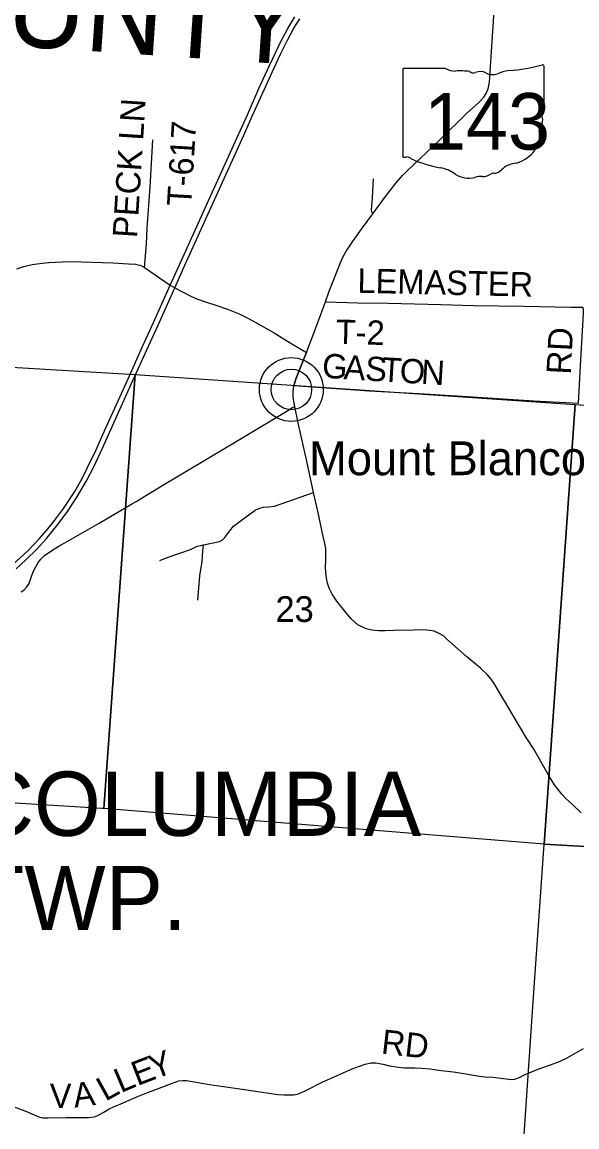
# Model space of a CAD drawing. Extents: x 0 to 34, y 0 to 22.
# Drawn here: x 6.101 to 7.394, y 18.062 to 20.64 of the extents above; entities that cross this region are included whole.
import ezdxf

# ---------------------------------------------------------------- set-up
doc = ezdxf.new("R2010")
doc.units = 0
for name, color, linetype in [('GM_X_Corporation', 7, 'Continuous'), ('GM_X_County_Road', 7, 'Continuous'), ('GM_X_County_Text', 7, 'Continuous'), ('GM_X_Section_Text', 7, 'Continuous'), ('GM_X_State_Location', 7, 'Continuous'), ('GM_X_State_Route', 7, 'Continuous'), ('GM_X_State_Shield', 7, 'Continuous'), ('GM_X_Township_Road', 7, 'Continuous'), ('GM_X_Township_Road_Text', 7, 'Continuous'), ('GM_X_Township_Text', 7, 'Continuous'), ('GM_X_Unincorporated', 7, 'Continuous'), ('GM_X_Unincorporated_Location', 7, 'Continuous'), ('GM_X_Unincorporated_Text', 7, 'Continuous')]:
    doc.layers.add(name, color=color, linetype=linetype)

msp = doc.modelspace()

# ---------------------------------------------------------------- linework, layer by layer
at = {"layer": 'GM_X_Corporation'}
for points in [[(6.3643, 19.8173), (6.291, 18.8048), (6.2863, 18.8051), (5.2756, 18.8667), (5.342, 19.878)], [(6.3643, 19.8173), (7.3904, 19.7475), (7.3179, 18.7214), (6.291, 18.8048)], [(7.3904, 19.7475), (8.4063, 19.6773), (8.3303, 18.6644), (7.3179, 18.7214)], [(7.3179, 18.7214), (8.3303, 18.6644), (8.2967, 18.2357), (8.2648, 17.8281), (8.2474, 17.6405), (7.6907, 17.673), (7.2488, 17.7032), (7.2611, 17.894), (7.2923, 18.3534)]]:
    msp.add_lwpolyline(points, close=True, dxfattribs=at)
at = {"layer": 'GM_X_County_Road'}
for points in [[(6.1988, 19.4239), (6.28, 19.4706), (6.3577, 19.5168), (6.3662, 19.5214), (6.4284, 19.5592), (6.4905, 19.5959), (6.6033, 19.6637), (6.7203, 19.7333), (6.731, 19.7408), (6.7363, 19.7428)], [(6.0981, 19.3103), (6.1045, 19.3142), (6.1111, 19.3214), (6.1162, 19.3284), (6.1264, 19.3567), (6.1323, 19.3689), (6.1381, 19.3792), (6.1445, 19.3869), (6.1532, 19.3952), (6.1702, 19.4072), (6.185, 19.416), (6.1988, 19.4239)]]:
    msp.add_lwpolyline(points, dxfattribs=at)
at = {"layer": 'GM_X_State_Route'}
for points in [[(6.8765, 20.1348), (6.8917, 20.1563), (6.9187, 20.1927), (6.9454, 20.2299), (6.972, 20.264), (6.9879, 20.2817), (6.9976, 20.2919), (7.0749, 20.3652), (7.1375, 20.4273), (7.1647, 20.4515), (7.1775, 20.4643), (7.1829, 20.4732), (7.1873, 20.4837), (7.1902, 20.4999), (7.1949, 20.5711), (7.2038, 20.701), (7.211, 20.7857)], [(6.067, 19.3632), (6.1157, 19.408), (6.1404, 19.434), (6.1572, 19.4536), (6.1766, 19.4773), (6.1953, 19.5027), (6.2233, 19.5449), (6.2397, 19.5735), (6.2519, 19.5972), (6.2724, 19.6402), (6.2887, 19.6773), (6.3361, 19.782), (6.3482, 19.8077), (6.3817, 19.8831), (6.4069, 19.939), (6.4458, 20.0256), (6.4674, 20.0733), (6.5366, 20.2263), (6.5942, 20.3534), (6.6013, 20.3691), (6.6258, 20.4236), (6.653, 20.4845), (6.6775, 20.5388), (6.7046, 20.5958), (6.7204, 20.6247), (6.7367, 20.6518)], [(6.087, 19.3643), (6.1094, 19.3847), (6.135, 19.4101), (6.1576, 19.4351), (6.1843, 19.4676), (6.2064, 19.498), (6.2278, 19.5294), (6.2511, 19.5694), (6.2685, 19.6039), (6.2877, 19.6453), (6.355, 19.7949), (6.4037, 19.9024), (6.4141, 19.9238), (6.4568, 20.0197), (6.4804, 20.0729), (6.5496, 20.2252), (6.618, 20.376), (6.6373, 20.4204), (6.6842, 20.5243), (6.7031, 20.5648), (6.7193, 20.5975), (6.7343, 20.6255), (6.7479, 20.6473)], [(6.7636, 19.869), (6.7903, 19.939), (6.8078, 19.987), (6.8167, 20.012), (6.8442, 20.0805), (6.8485, 20.0913), (6.8555, 20.1035), (6.8712, 20.1274), (6.8765, 20.1348)], [(6.7345, 19.7916), (6.7399, 19.8093), (6.7613, 19.8636), (6.7636, 19.869)], [(7.4042, 18.795), (7.3853, 18.8123), (7.3687, 18.8283), (7.3595, 18.838), (7.3422, 18.8597), (7.3296, 18.8801), (7.2937, 18.9433), (7.2763, 18.9708), (7.2462, 19.0206), (7.2013, 19.0967), (7.1941, 19.1065), (7.1856, 19.1164), (7.1692, 19.132), (7.1374, 19.1589), (7.1042, 19.1882), (7.0911, 19.2001), (7.083, 19.2076), (7.0734, 19.2133), (7.0614, 19.2184), (7.051, 19.2205), (7.0371, 19.2215), (7.0136, 19.2213), (6.9673, 19.2203), (6.9475, 19.2197), (6.9314, 19.2196), (6.9161, 19.2207), (6.9031, 19.2239), (6.8837, 19.2333), (6.868, 19.2474), (6.8529, 19.2655), (6.8346, 19.289), (6.8237, 19.3053), (6.817, 19.3188), (6.8131, 19.331), (6.8103, 19.343), (6.8087, 19.3547), (6.8084, 19.3681), (6.8087, 19.3842), (6.8089, 19.401), (6.8085, 19.4112), (6.8066, 19.4234), (6.8027, 19.4393), (6.7899, 19.4987), (6.7803, 19.5424), (6.7642, 19.6155), (6.7454, 19.7012), (6.7363, 19.7428), (6.7345, 19.7548), (6.733, 19.767), (6.733, 19.7769), (6.7332, 19.7843), (6.7345, 19.7916)]]:
    msp.add_lwpolyline(points, dxfattribs=at)
at = {"layer": 'GM_X_State_Shield'}
for p, q in [((6.988, 20.5284), (6.988, 20.3283)), ((7.0878, 20.5318), (6.9913, 20.5318)), ((7.3176, 20.4321), (7.3176, 20.5368)), ((7.3176, 20.4321), (7.3176, 20.4321))]:
    msp.add_line(p, q, dxfattribs=at)
for centre, major_axis, start_param, end_param in [((6.9918, 20.5288), (0.00382, 0), 1.712693, 3.28349), ((7.1108, 20.5551), (0.037, 0), 4.042523, 4.731795), ((7.1231, 20.4195), (0.133, 0), 1.404758, 1.657858), ((7.1532, 20.5299), (0.0107, 0), 3.836095, 5.185415), ((7.1689, 20.5067), (0.0222, 0), 0.950623, 2.079405), ((7.1976, 20.5385), (0.0267, 0), 4.081561, 5.145723), ((7.2448, 20.4707), (0.0703, 0), 1.699011, 2.107814), ((7.2002, 20.8047), (0.3495, 0), 4.814394, 5.042369), ((7.314, 20.5372), (0.00367, 0), 6.141152, 7.989035), ((7.3168, 20.4244), (0.00568, 0), 1.883978, 3.671073), ((7.2806, 20.4112), (0.0341, 0), 5.934695, 6.695948), ((7.3137, 20.4317), (0.00393, 0), 5.05454, 6.418171), ((7.3308, 20.3883), (0.0248, 0), 2.387724, 3.262537), ((7.2198, 20.375), (0.0874, 0), 5.101752, 6.440018), ((6.9918, 20.3278), (0.00385, 0), 3.00124, 4.508301), ((6.9924, 20.3483), (0.0294, 0), 4.665946, 4.897461), ((6.9984, 20.3167), (0.0106, 0), 0.519207, 1.627899), ((7.1323, 20.4965), (0.2524, 0), 4.195997, 4.488961), ((7.057, 20.2384), (0.079, 0), 0.823519, 1.323587), ((7.196, 20.3089), (0.0282, 0), 4.937069, 5.64225), ((7.2567, 20.2721), (0.0479, 0), 1.647645, 2.488434), ((7.1424, 20.3157), (0.0501, 0), 4.026481, 4.996735), ((7.1714, 20.2466), (0.0412, 0), 1.495662, 1.94098), ((7.175, 20.3008), (0.0267, 0), 4.691044, 5.507374), ((7.1992, 20.2814), (0.00752, 0), 1.147584, 2.315152)]:
    msp.add_ellipse(centre, major_axis=major_axis, ratio=0.8, start_param=start_param, end_param=end_param, dxfattribs=at)
at = {"layer": 'GM_X_Township_Road'}
msp.add_line((6.3861, 20.0674), (6.4458, 20.0256), dxfattribs=at)
for points in [[(6.3861, 20.0674), (6.3904, 20.1213), (6.3925, 20.1594), (6.3991, 20.255), (6.4057, 20.365)], [(6.9187, 20.1927), (6.9164, 20.1973), (6.915, 20.2014), (6.9173, 20.2305), (6.9196, 20.2737)], [(6.0885, 20.0641), (6.1048, 20.0698), (6.1242, 20.074), (6.1475, 20.0775), (6.1628, 20.0788), (6.1937, 20.0805), (6.2152, 20.0814), (6.3125, 20.0778), (6.3485, 20.076), (6.3648, 20.075), (6.3707, 20.0737), (6.3753, 20.0726), (6.3789, 20.0709), (6.3861, 20.0674)], [(6.4458, 20.0256), (6.4568, 20.0197), (6.4912, 20.0016), (6.5058, 19.9952), (6.5285, 19.9872), (6.5548, 19.9783), (6.5798, 19.97), (6.607, 19.9587), (6.6289, 19.9481), (6.6508, 19.9357), (6.688, 19.9145), (6.7256, 19.8913), (6.7636, 19.869)], [(6.8078, 19.987), (6.8835, 19.9849), (6.955, 19.9837), (7.0769, 19.9809), (7.1529, 19.9784), (7.2703, 19.9768), (7.3804, 19.9749), (7.408, 19.9745)], [(6.7345, 19.7916), (6.8105, 19.7864), (6.91, 19.7796), (7.0256, 19.7732), (7.1508, 19.7653), (7.198, 19.7624), (7.2941, 19.7563), (7.3981, 19.7503), (7.4029, 19.8375), (7.41, 19.9599), (7.41, 19.9692), (7.408, 19.9745)], [(6.7636, 19.869), (6.7613, 19.8636), (6.7399, 19.8093), (6.7345, 19.7916)], [(6.5226, 19.4201), (6.5236, 19.4203), (6.5611, 19.4279), (6.5673, 19.4307), (6.5735, 19.4374), (6.5849, 19.4526), (6.5939, 19.464), (6.6091, 19.4754), (6.6442, 19.501), (6.6523, 19.5048), (6.6627, 19.5076), (6.676, 19.5091), (6.6893, 19.51), (6.7803, 19.5424)], [(6.4215, 19.3837), (6.4353, 19.3889), (6.4566, 19.397), (6.478, 19.4036), (6.4951, 19.4103), (6.5089, 19.4169), (6.517, 19.4188), (6.5226, 19.4201)], [(6.5103, 19.2906), (6.5151, 19.3481), (6.5203, 19.3813), (6.5222, 19.4051), (6.5236, 19.4203)], [(6.0732, 18.1122), (6.1007, 18.1016), (6.1146, 18.0963), (6.1303, 18.0891), (6.1397, 18.0852), (6.1487, 18.0834), (6.1609, 18.083), (6.2025, 18.0836), (6.219, 18.0836), (6.2553, 18.0842), (6.2694, 18.0854), (6.2773, 18.0883), (6.29, 18.0958), (6.3037, 18.1042), (6.3141, 18.1085), (6.3289, 18.1146), (6.3451, 18.1221), (6.372, 18.134), (6.3952, 18.1428), (6.4099, 18.1487), (6.4266, 18.1546), (6.4493, 18.1634), (6.4664, 18.1693), (6.4752, 18.1705), (6.4842, 18.1701), (6.4931, 18.1685), (6.5015, 18.1672), (6.5194, 18.1638), (6.5376, 18.1605), (6.619, 18.1489), (6.6551, 18.1434), (6.6973, 18.1377), (6.7108, 18.1368), (6.7234, 18.1364), (6.7346, 18.1368), (6.7418, 18.1383), (6.7503, 18.1417), (6.764, 18.1479), (6.8001, 18.1662), (6.8284, 18.1786), (6.87, 18.1974), (6.8874, 18.2039), (6.9002, 18.2086), (6.9141, 18.2111), (6.9245, 18.2117), (6.9429, 18.2082), (6.9573, 18.2046), (6.9783, 18.2013), (6.9926, 18.2001), (7.0165, 18.2001), (7.0316, 18.1993), (7.0512, 18.1972), (7.0779, 18.1933), (7.1062, 18.1905), (7.1403, 18.185), (7.1521, 18.1827), (7.1672, 18.1799), (7.1795, 18.1784), (7.1988, 18.1778), (7.2229, 18.1752), (7.2415, 18.1727), (7.2496, 18.1733), (7.258, 18.1766), (7.2767, 18.1854), (7.3102, 18.1991), (7.3324, 18.2064), (7.3536, 18.2147), (7.3714, 18.2229), (7.3881, 18.2323), (7.4099, 18.2445)]]:
    msp.add_lwpolyline(points, dxfattribs=at)
at = {"layer": 'GM_X_Unincorporated'}
for radius in [0.0744, 0.0472]:
    msp.add_circle((6.7285, 19.7826), radius, dxfattribs=at)
at = {"layer": 'GM_X_Unincorporated_Location'}
msp.add_line((6.7285, 19.7826), (6.7285, 19.7826), dxfattribs=at)

# ---------------------------------------------------------------- texts
at = {"layer": 'GM_X_County_Text'}
msp.add_text('MEIGS COUNTY', height=0.189394, rotation=356.1113, dxfattribs=at).set_placement((4.7976, 20.6717))
at = {"layer": 'GM_X_Section_Text'}
msp.add_text('23', height=0.06, rotation=0, dxfattribs=at).set_placement((6.6914, 19.2402))
at = {"layer": 'GM_X_State_Location'}
msp.add_text('143', height=0.000189, rotation=0, dxfattribs=at).set_placement((7.0823, 20.4013))
for s in ['s', 'r']:
    msp.add_text(s, height=0.000189, dxfattribs=at).set_placement((7.1491, 20.415))
at = {"layer": 'GM_X_State_Shield'}
msp.add_text('143', height=0.13184, dxfattribs=at).set_placement((7.0375, 20.3424))
at = {"layer": 'GM_X_Township_Road_Text'}
for s, height, rotation, p in [('PECK LN', 0.05682, 86.3714, (6.3683, 20.1351)), ('T-617', 0.05682, 86.6338, (6.4949, 20.209)), ('LEMASTER', 0.05682, 358.7066, (6.8821, 20.0083)), ('T-2', 0.05682, 358.5687, (6.8315, 19.8891)), ('RD', 0.05682, 87.0658, (7.3799, 19.8166)), ('G', 0.0568, 355.6865, (6.7986, 19.8106)), ('A', 0.0568, 356.4682, (6.8493, 19.8068)), ('S', 0.0568, 356.4771, (6.8992, 19.8037)), ('T', 0.0568, 356.4815, (6.9375, 19.8014)), ('O', 0.0568, 356.4789, (6.9799, 19.7988)), ('N', 0.0568, 356.4814, (7.0298, 19.7957)), ('RD', 0.05682, 353.6073, (6.9364, 18.2332)), ('E', 0.0568, 21.0907, (6.3693, 18.1569)), ('Y', 0.0568, 20.0917, (6.4087, 18.1721)), ('L', 0.0568, 29.0605, (6.2949, 18.1205)), ('L', 0.0568, 23.0286, (6.3306, 18.1404)), ('V', 0.0568, 0.5282, (6.1657, 18.1058)), ('A', 0.0568, 7.3459, (6.2231, 18.1068))]:
    msp.add_text(s, height=height, rotation=rotation, dxfattribs=at).set_placement(p)
at = {"layer": 'GM_X_Township_Text'}
for s, p in [('COLUMBIA', (5.9834, 18.741)), ('TWP.', (5.9834, 18.521))]:
    msp.add_text(s, height=0.15, rotation=0, dxfattribs=at).set_placement(p)
at = {"layer": 'GM_X_Unincorporated_Text'}
msp.add_text('Mount Blanco', height=0.078977, rotation=0, dxfattribs=at).set_placement((6.7698, 19.5826))

doc.saveas('drawing.dxf')
